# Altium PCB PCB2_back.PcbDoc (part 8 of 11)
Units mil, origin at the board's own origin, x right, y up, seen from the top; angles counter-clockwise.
Board outline 6299 x 3937 mil, 4 copper layers (TopLayer, GROUND, VCC, BottomLayer); 290 components, 470 nets, 2252 pads, 825 vias.
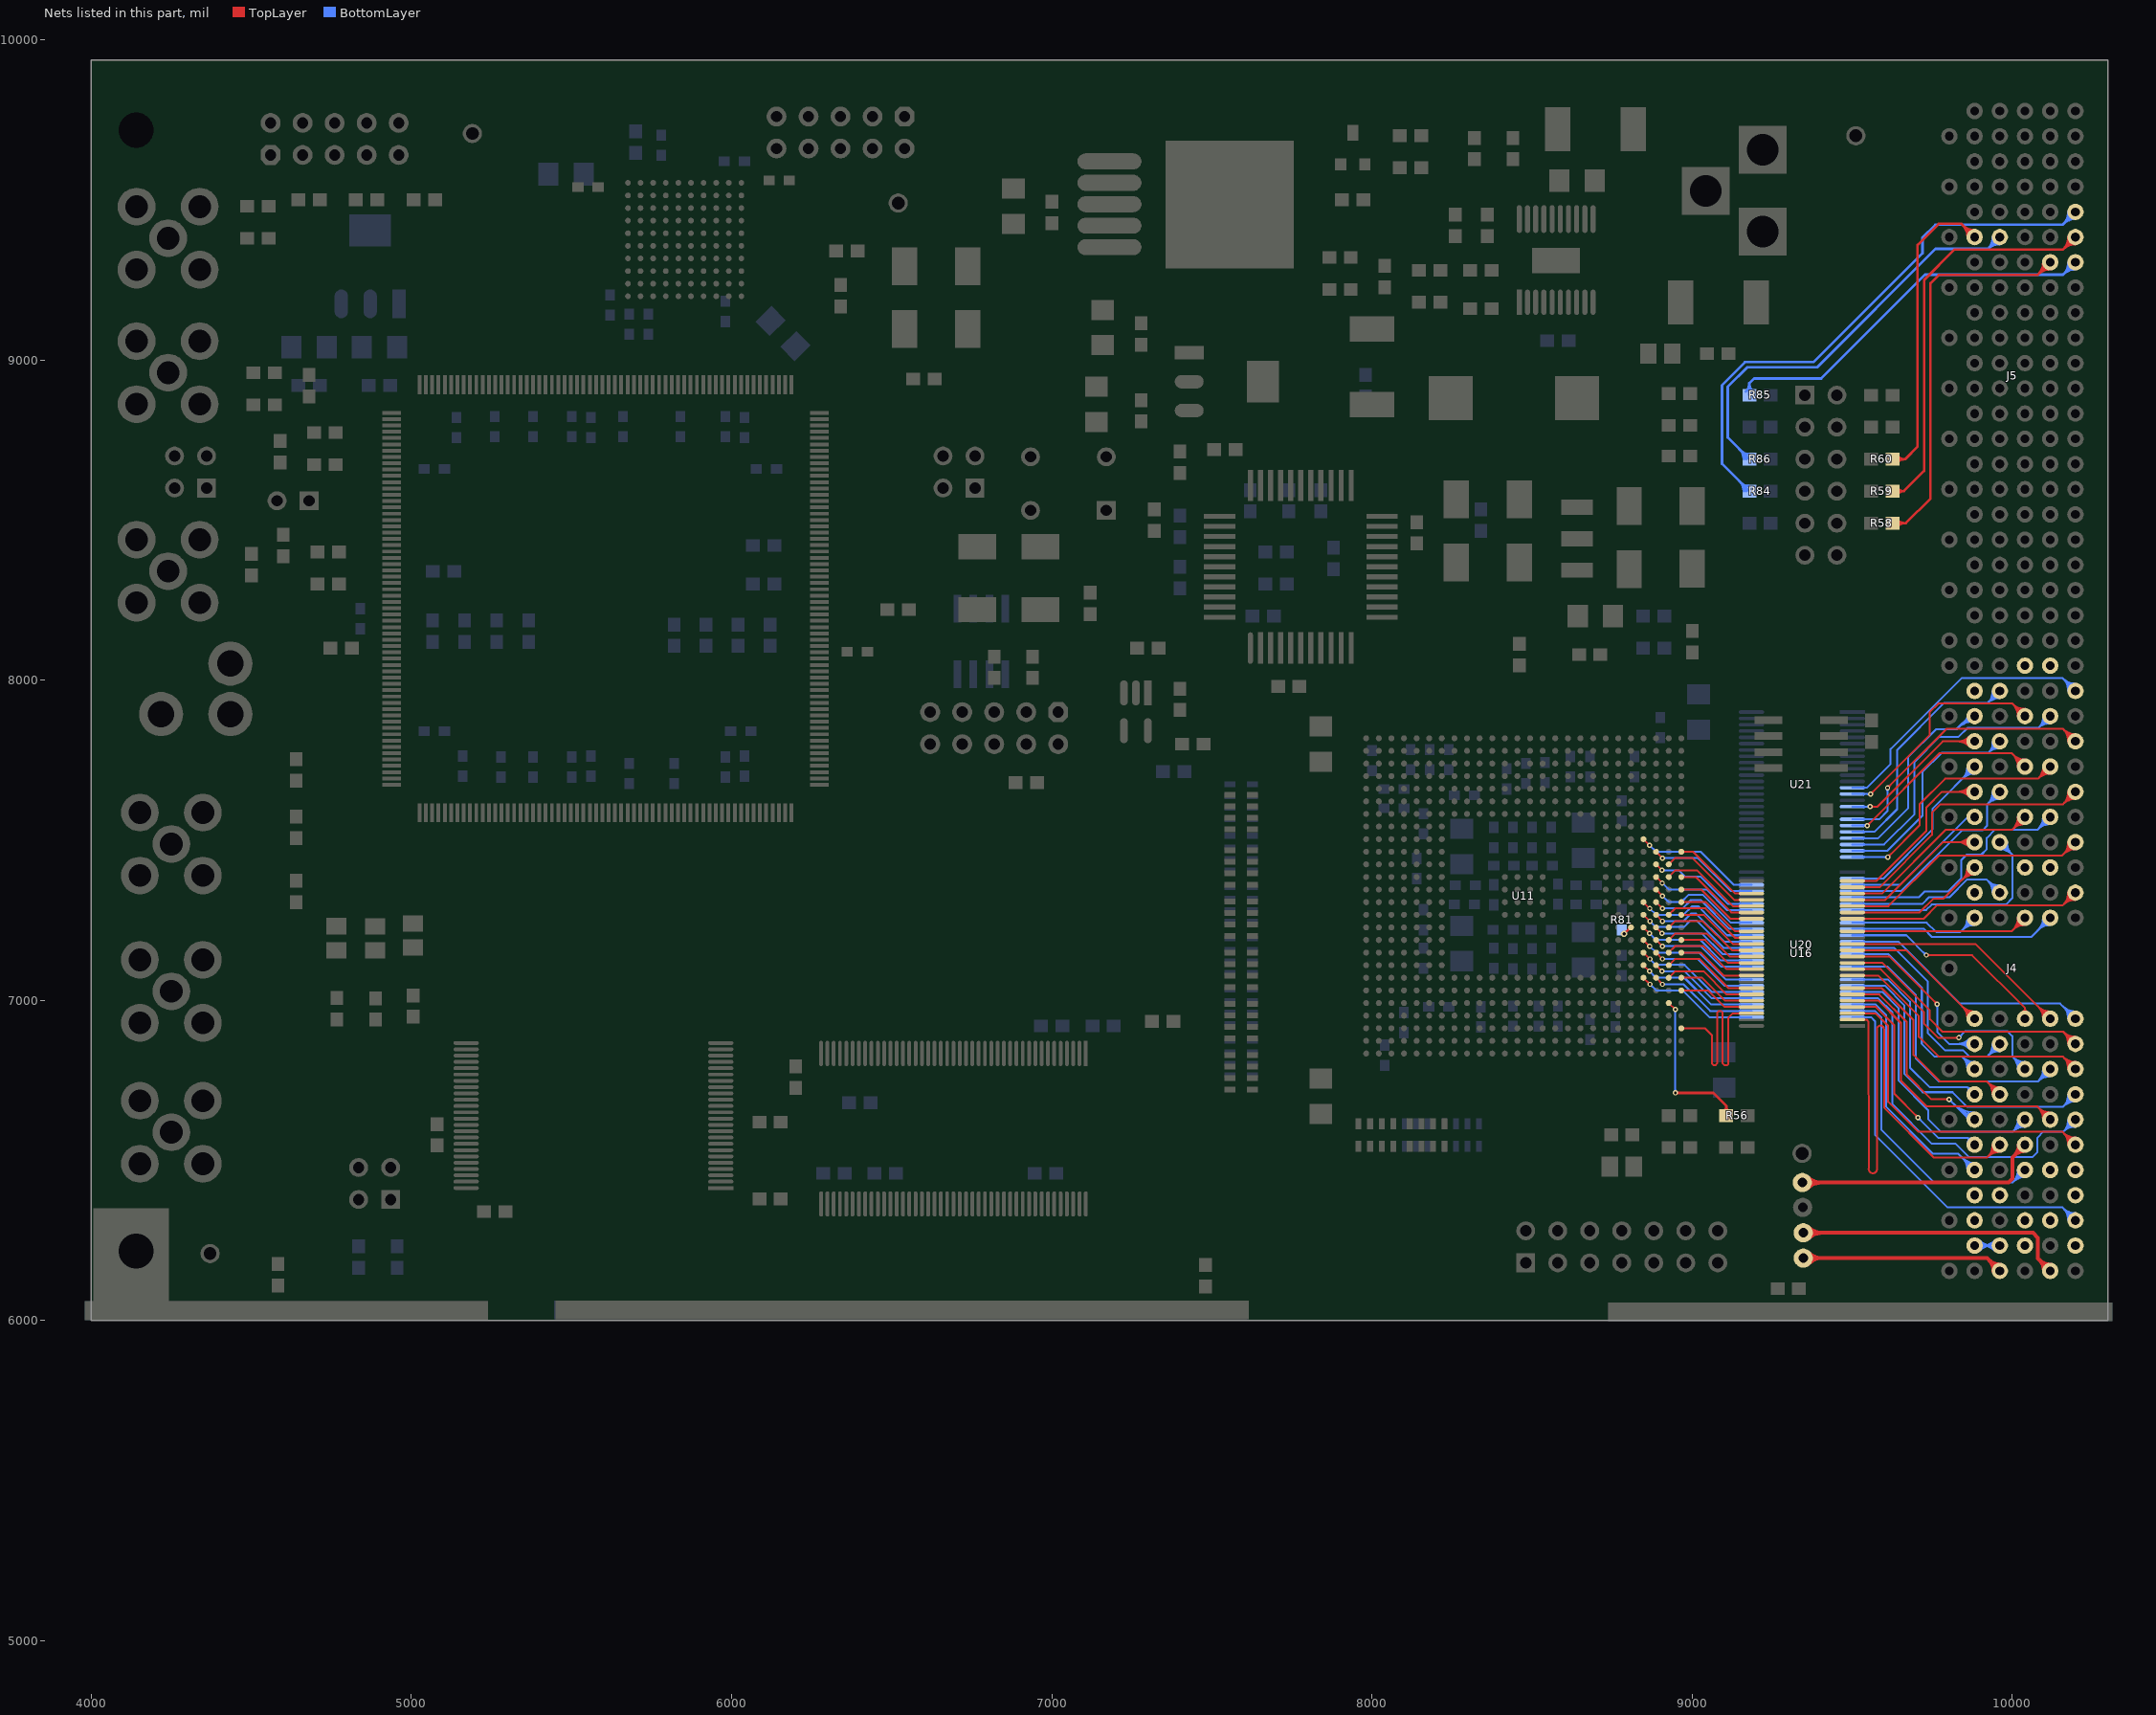
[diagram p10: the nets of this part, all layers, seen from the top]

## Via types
v1: diameter 16, hole 8, TopLayer to BottomLayer, 408 vias
v2: diameter 20, hole 10, TopLayer to BottomLayer, 221 vias
v3: diameter 24, hole 12, TopLayer to BottomLayer, 194 vias
v4: diameter 56.69, hole 56.69, TopLayer to BottomLayer, 2 vias

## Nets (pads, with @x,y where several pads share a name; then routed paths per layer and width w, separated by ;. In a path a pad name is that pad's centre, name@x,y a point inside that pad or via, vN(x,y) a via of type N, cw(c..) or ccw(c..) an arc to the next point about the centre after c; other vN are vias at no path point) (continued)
P_AD13: U11.U3 U20.45 | length 358.2
  TopLayer w6: U11.U3@8887.26,7463.92 v1(8907.18,7444)
  BottomLayer w6: v1(8907.18,7444) 9018,7444 9121.06,7340.94 U20.45@9185.04,7340.94 ; U20.45@9149.4,7339.17 ccw(c9145.12,7334.88) 9145.12,7340.95 ccw(c9145.12,7347.01) U20.45@9149.4,7342.72
P_AD14: U11.U1 U16.27 | length 282.6
  TopLayer w6: U11.U1@8966,7463.92 9003.08,7463.92 9133.61,7333.39 U16.27@9185.04,7333.39 ; U16.27@9149.4,7331.61 ccw(c9145.12,7327.32) 9145.12,7333.39 ccw(c9145.12,7339.45) U16.27@9149.4,7335.16
P_AD15: U11.T3 U20.43 | length 358.2
  TopLayer w6: U11.T3@8887.26,7424.55 v1(8905.81,7406)
  BottomLayer w6: v1(8905.81,7406) 8958,7406 8977.45,7386.55 9025.45,7386.55 9110.42,7301.57 U20.43@9185.04,7301.57 ; U20.43@9149.4,7299.8 ccw(c9145.12,7295.51) 9145.12,7301.58 ccw(c9145.12,7307.64) U20.43@9149.4,7303.35
P_AD16: U11.M3 U20.37 | length 361.8
  TopLayer w6: U11.M3@8887.26,7267.07 v1(8907.33,7247)
  BottomLayer w6: v1(8907.33,7247) 8972,7247 8996,7271 9012,7271 9099.53,7183.47 U20.37@9185.04,7183.47 ; U20.37@9149.4,7181.69 ccw(c9145.12,7177.4) 9145.12,7183.47 ccw(c9145.12,7189.53) U20.37@9149.4,7185.24
P_AD17: U11.M2 U16.34 | length 314.1
  TopLayer w6: U11.M2@8926.63,7267.07 8946.56,7287 9042,7287 9133.41,7195.59 U16.34@9185.04,7195.59 ; U16.34@9149.4,7193.81 ccw(c9145.12,7189.53) 9145.12,7195.59 ccw(c9145.12,7201.65) U16.34@9149.4,7197.37
P_AD18: U11.M4 U20.36 | length 405.2
  TopLayer w6: U11.M4@8847.89,7267.07 v1(8867.96,7247)
  BottomLayer w6: v1(8867.96,7247) 8885.96,7229 8974,7229 8993,7248 9014,7248 9098.22,7163.78 U20.36@9185.04,7163.78 ; U20.36@9149.4,7162 ccw(c9145.12,7157.72) 9145.12,7163.78 ccw(c9145.12,7169.84) U20.36@9149.4,7165.56
P_AD19: U11.L2 U16.36 | length 313.5
  TopLayer w6: U11.L2@8926.63,7227.7 8945.93,7247 9033,7247 9123.78,7156.22 U16.36@9185.04,7156.22 ; U16.36@9149.4,7154.44 ccw(c9145.12,7150.16) 9145.12,7156.22 ccw(c9145.12,7162.28) U16.36@9149.4,7158
P_AD20: U11.L3 U20.35 | length 341.9
  TopLayer w6: U11.L3@8887.26,7227.7 v1(8905.96,7209)
  BottomLayer w6: v1(8905.96,7209) 9030,7209 9094.91,7144.1 U20.35@9185.04,7144.1 ; U20.35@9149.4,7142.32 ccw(c9145.12,7138.03) 9145.12,7144.1 ccw(c9145.12,7150.16) U20.35@9149.4,7145.87
P_AD21: U11.K2 U16.37 | length 306.5
  TopLayer w6: U11.K2@8926.63,7188.33 8947.3,7209 9045,7209 9117.47,7136.53 U16.37@9185.04,7136.53 ; U16.37@9149.4,7134.76 ccw(c9145.12,7130.47) 9145.12,7136.53 ccw(c9145.12,7142.6) U16.37@9149.4,7138.31
P_AD22: U11.L4 U20.34 | length 389.5
  TopLayer w6: U11.L4@8847.89,7227.7 v1(8866.59,7209)
  BottomLayer w6: v1(8866.59,7209) 8886.59,7189 9025,7189 9089.59,7124.41 U20.34@9185.04,7124.41 ; U20.34@9149.4,7122.63 ccw(c9145.12,7118.35) 9145.12,7124.41 ccw(c9145.12,7130.47) U20.34@9149.4,7126.19
P_AD23: U11.K1 U16.38 | length 258.2
  TopLayer w6: U11.K1@8966,7188.33 9040.67,7188.33 9112.15,7116.85 U16.38@9185.04,7116.85 ; U16.38@9149.4,7115.07 ccw(c9145.12,7110.79) 9145.12,7116.85 ccw(c9145.12,7122.91) U16.38@9149.4,7118.63
P_AD24: U11.K4 U20.31 | length 397.6
  TopLayer w6: U11.K4@8847.89,7188.33 v1(8867.22,7169)
  BottomLayer w6: v1(8867.22,7169) 8887.22,7149 9021,7149 9104.65,7065.35 U20.31@9185.04,7065.35 ; U20.31@9149.4,7063.58 ccw(c9145.12,7059.29) 9145.12,7065.36 ccw(c9145.12,7071.42) U20.31@9149.4,7067.13
P_AD25: U11.J1 U16.40 | length 258.2
  TopLayer w6: U11.J1@8966,7148.96 9026.04,7148.96 9097.52,7077.48 U16.40@9185.04,7077.48 ; U16.40@9149.4,7075.7 ccw(c9145.12,7071.42) 9145.12,7077.48 ccw(c9145.12,7083.54) U16.40@9149.4,7079.26
P_AD26: U11.J3 U20.30 | length 350.1
  TopLayer w6: U11.J3@8887.26,7148.96 v1(8907.22,7129)
  BottomLayer w6: v1(8907.22,7129) 9017,7129 9100.33,7045.67 U20.30@9185.04,7045.67 ; U20.30@9149.4,7043.89 ccw(c9145.12,7039.61) 9145.12,7045.67 ccw(c9145.12,7051.73) U20.30@9149.4,7047.45
P_AD27: U11.H2 U16.42 | length 313.6
  TopLayer w6: U11.H2@8926.63,7109.59 8946.04,7129 9023,7129 9113.89,7038.11 U16.42@9185.04,7038.11 ; U16.42@9149.4,7036.33 ccw(c9145.12,7032.05) 9145.12,7038.11 ccw(c9145.12,7044.17) U16.42@9149.4,7039.89
P_AD28: U11.J4 U20.29 | length 397.6
  TopLayer w6: U11.J4@8847.89,7148.96 v1(8867.85,7129)
  BottomLayer w6: v1(8867.85,7129) 8885.85,7111 8976,7111 9061.01,7025.98 U20.29@9185.04,7025.98 ; U20.29@9149.4,7024.21 ccw(c9145.12,7019.92) 9145.12,7025.99 ccw(c9145.12,7032.05) U20.29@9149.4,7027.76
P_AD29: U11.G2 U16.43 | length 306.6
  TopLayer w6: U11.G2@8926.63,7070.22 8947.41,7091 9035,7091 9107.58,7018.43 U16.43@9185.04,7018.43 ; U16.43@9149.4,7016.65 ccw(c9145.12,7012.36) 9145.12,7018.43 ccw(c9145.12,7024.49) U16.43@9149.4,7020.2
P_AD30: U11.H3 U20.28 | length 350.1
  TopLayer w6: U11.H3@8887.26,7109.59 v1(8905.85,7091)
  BottomLayer w6: v1(8905.85,7091) 8976,7091 9060.7,7006.3 U20.28@9185.04,7006.3 ; U20.28@9149.4,7004.52 ccw(c9145.12,7000.24) 9145.12,7006.3 ccw(c9145.12,7012.36) U20.28@9149.4,7008.08
P_AD31: U11.G1 U16.44 | length 258.2
  TopLayer w6: U11.G1@8966,7070.22 9030.78,7070.22 9102.26,6998.74 U16.44@9185.04,6998.74 ; U16.44@9149.4,6996.96 ccw(c9145.12,6992.68) 9145.12,6998.74 ccw(c9145.12,7004.8) U16.44@9149.4,7000.52
P_CBE0: U11.V4 U20.46 | length 405.8
  TopLayer w6: U11.V4@8847.89,7503.29 v1(8867.18,7484)
  BottomLayer w6: v1(8867.18,7484) 8887.18,7464 9027,7464 9130.37,7360.63 U20.46@9185.04,7360.63 ; U20.46@9149.4,7358.85 ccw(c9145.12,7354.57) 9145.12,7360.63 ccw(c9145.12,7366.69) U20.46@9149.4,7362.41
P_CBE1: U11.T2 U16.28 | length 330
  TopLayer w6: U11.T2@8926.63,7424.55 8946.08,7444 9001,7444 9131.3,7313.7 U16.28@9185.04,7313.7 ; U16.28@9149.4,7311.92 ccw(c9145.12,7307.64) 9145.12,7313.7 ccw(c9145.12,7319.76) U16.28@9149.4,7315.48
P_CBE2: U11.M1 U16.35 | length 266.3
  TopLayer w6: U11.M1@8966,7267.07 9035.93,7267.07 9127.09,7175.9 U16.35@9185.04,7175.9 ; U16.35@9149.4,7174.13 ccw(c9145.12,7169.84) 9145.12,7175.91 ccw(c9145.12,7181.97) U16.35@9149.4,7177.68
P_CBE3: U11.J2 U16.39 | length 306
  TopLayer w6: U11.J2@8926.63,7148.96 8946.67,7169 9035,7169 9106.83,7097.16 U16.39@9185.04,7097.16 ; U16.39@9149.4,7095.39 ccw(c9145.12,7091.1) 9145.12,7097.16 ccw(c9145.12,7103.23) U16.39@9149.4,7098.94
P_CLK: U11.C1 U16.46 | length 805.9
  TopLayer w6: U11.C1@8966,6912.74 9039.26,6912.74 9062,6890 9062,6802 9066,6798 9073,6798 9078,6803 9078,6961 9084,6967 9090,6967 9095,6962 9095,6803 9101,6797 9109,6797 9113,6801 9113,6946 9126.37,6959.37 U16.46@9185.04,6959.37 ; U16.46@9149.4,6957.59 ccw(c9145.12,6953.31) 9145.12,6959.37 ccw(c9145.12,6965.43) U16.46@9149.4,6961.15
P_DEVSEL: U11.P1 U16.31 | length 266.3
  TopLayer w6: U11.P1@8966,7345.81 9028.19,7345.81 9119.35,7254.65 U16.31@9185.04,7254.65 ; U16.31@9149.4,7252.87 ccw(c9145.12,7248.58) 9145.12,7254.65 ccw(c9145.12,7260.71) U16.31@9149.4,7256.42
P_EN: R56.1 U11.E2 | length 571.2
  TopLayer w6: U11.E2@8926.63,6991.48 v1(8947,6971.11)
  TopLayer w8: v1(8947,6711) 9066,6711 9106.54,6670.46 ; v1@8949.83,6708.17 cw(c8956.66,6701.34) 8956.66,6711 cw(c8956.66,6720.66) v1@8949.83,6713.83 ; R56.1@9097.42,6652.77 ccw(c9084.79,6670.46) 9106.54,6670.46 ; R56.1@9106.54,6640 9106.54,6670.46 ; R56.1@9115.65,6652.77 cw(c9128.28,6670.46) 9106.54,6670.46
  BottomLayer w6: v1@8943.46,6714.54 ccw(c8934.93,6723.07) 8947,6723.07 ccw(c8959.07,6723.07) v1@8950.54,6714.54 ; v1(8947,6711) v1(8947,6971.11)
P_FRAME: U11.N4 U20.38 | length 411.3
  TopLayer w6: U11.N4@8847.89,7306.44 v1(8867.33,7287)
  BottomLayer w6: v1(8867.33,7287) 8887.33,7267 8973,7267 8999,7293 9020,7293 9036,7277 ; 9035.5,7276.5 9108.85,7203.15 U20.38@9185.04,7203.15 ; U20.38@9149.4,7201.37 ccw(c9145.12,7197.09) 9145.12,7203.15 ccw(c9145.12,7209.21) U20.38@9149.4,7204.93
P_GNT: U11.H4 U20.27 | length 397.6
  TopLayer w6: U11.H4@8847.89,7109.59 v1(8866.48,7091)
  BottomLayer w6: v1(8866.48,7091) 8886.48,7071 8975,7071 9059.39,6986.61 U20.27@9185.04,6986.61 ; U20.27@9149.4,6984.84 ccw(c9145.12,6980.55) 9145.12,6986.62 ccw(c9145.12,6992.68) U20.27@9149.4,6988.39
P_IDSEL: U11.K3 U20.33 | length 341.9
  TopLayer w6: U11.K3@8887.26,7188.33 v1(8906.59,7169)
  BottomLayer w6: v1(8906.59,7169) 9026,7169 9090.27,7104.73 U20.33@9185.04,7104.73 ; U20.33@9149.4,7102.95 ccw(c9145.12,7098.66) 9145.12,7104.73 ccw(c9145.12,7110.79) U20.33@9149.4,7106.5
P_INTA: U11.G4 U20.25 | length 397.6
  TopLayer w6: U11.G4@8847.89,7070.22 v1(8868.11,7050)
  BottomLayer w6: v1(8868.11,7050) 8887.11,7031 8970,7031 9053.75,6947.24 U20.25@9185.04,6947.24 ; U20.25@9149.4,6945.47 ccw(c9145.12,6941.18) 9145.12,6947.24 ccw(c9145.12,6953.31) U20.25@9149.4,6949.02
P_IRDY: U11.N1 U16.33 | length 266.3
  TopLayer w6: U11.N1@8966,7306.44 9042.56,7306.44 9133.73,7215.27 U16.33@9185.04,7215.27 ; U16.33@9149.4,7213.5 ccw(c9145.12,7209.21) 9145.12,7215.28 ccw(c9145.12,7221.34) U16.33@9149.4,7217.05
P_PAR: U11.P3 U20.40 | length 368.3
  TopLayer w6: U11.P3@8887.26,7345.81 v1(8907.07,7326)
  BottomLayer w6: v1(8907.07,7326) 8926.07,7307 8966,7307 8988,7329 9034,7329 9120.48,7242.52 U20.40@9185.04,7242.52 ; U20.40@9149.4,7240.74 ccw(c9145.12,7236.46) 9145.12,7242.52 ccw(c9145.12,7248.58) U20.40@9149.4,7244.3
P_PERR: U11.R1 U16.30 | length 274.5
  TopLayer w6: U11.R1@8966,7385.18 9010.82,7385.18 9121.67,7274.33 U16.30@9185.04,7274.33 ; U16.30@9149.4,7272.55 ccw(c9145.12,7268.27) 9145.12,7274.33 ccw(c9145.12,7280.39) U16.30@9149.4,7276.11
P_REQ: U11.F1 U16.45 | length 250
  TopLayer w6: U11.F1@8966,7030.85 9049.15,7030.85 9100.94,6979.06 U16.45@9185.04,6979.06 ; U16.45@9149.4,6977.28 ccw(c9145.12,6972.99) 9145.12,6979.06 ccw(c9145.12,6985.12) U16.45@9149.4,6980.83
P_RST: U11.G3 U20.26 | length 350.1
  TopLayer w6: U11.G3@8887.26,7070.22 v1(8907.48,7050)
  BottomLayer w6: v1(8907.48,7050) 8973,7050 9056.07,6966.93 U20.26@9185.04,6966.93 ; U20.26@9149.4,6965.15 ccw(c9145.12,6960.87) 9145.12,6966.93 ccw(c9145.12,6972.99) U20.26@9149.4,6968.71
P_SERR: U11.R2 U16.29 | length 322.1
  TopLayer w6: U11.R2@8926.63,7385.18 8946.45,7405 9016,7405 9126.99,7294.02 U16.29@9185.04,7294.02 ; U16.29@9149.4,7292.24 ccw(c9145.12,7287.95) 9145.12,7294.02 ccw(c9145.12,7300.08) U16.29@9149.4,7295.79
P_STOP: U11.R3 U20.42 | length 350.1
  TopLayer w6: U11.R3@8887.26,7385.18 v1(8906.44,7366)
  BottomLayer w6: v1(8906.44,7366) 8926.44,7346 9044,7346 9108.11,7281.89 U20.42@9185.04,7281.89 ; U20.42@9149.4,7280.11 ccw(c9145.12,7275.83) 9145.12,7281.89 ccw(c9145.12,7287.95) U20.42@9149.4,7283.67
P_TRDY: U11.N3 U20.39 | length 363.5
  TopLayer w6: U11.N3@8887.26,7306.44 v1(8906.7,7287)
  BottomLayer w6: v1(8906.7,7287) 8970,7287 8996,7313 9026,7313 9116.17,7222.84 U20.39@9185.04,7222.84 ; U20.39@9149.4,7221.06 ccw(c9145.12,7216.77) 9145.12,7222.84 ccw(c9145.12,7228.9) U20.39@9149.4,7224.61
PCI_EEAI: R81.1 U11.L5 | length 29.2
  TopLayer w8: v2(8787,7208) U11.L5@8808.52,7227.7
PXI_3.3V: J4.C6 pad.1@9344,6431 | length 948.5
  TopLayer w12: pad.1@9344,6431 9988,6431 10000,6443 10000,6509.51 J4.C6@10039.37,6548.88 ; pad.1@9360.97,6414.03 cw(c9401.94,6373.06) 9401.94,6431 cw(c9401.94,6488.94) pad.1@9360.97,6447.97 ; J4.C6@10019.78,6548.88 cw(c9972.48,6548.88) 10005.93,6515.44 cw(c10039.37,6482) J4.C6@10039.37,6529.29
PXI_+12V: J4.D1 pad.4 | length 795.4
  TopLayer w12: pad.4@9347,6195 9920.81,6195 J4.D1@9960.63,6155.18 ; pad.4@9363.97,6178.03 cw(c9404.94,6137.06) 9404.94,6195 cw(c9404.94,6252.94) pad.4@9363.97,6211.97 ; J4.D1@9941.04,6155.18 ccw(c9893.74,6155.18) 9927.19,6188.62 ccw(c9960.63,6222.07) J4.D1@9960.63,6174.77
PXI_-12V: J4.B1 pad.3 | length 1023.5
  TopLayer w12: pad.3@9347,6274 10064,6274 10080,6258 10080,6193.29 J4.B1@10118.11,6155.18 ; pad.3@9363.97,6257.03 cw(c9404.94,6216.06) 9404.94,6274 cw(c9404.94,6331.94) pad.3@9363.97,6290.97 ; J4.B1@10098.52,6155.18 ccw(c10051.22,6155.18) 10084.67,6188.62 ccw(c10118.11,6222.07) J4.B1@10118.11,6174.77
PXI_ACK64#: J4.E24
PXI_AD0: J4.D24 U21.20 | length 913.8
  BottomLayer w6: U21.20@9500,7525.98 9569,7525.98 9640,7596.98 9640,7782 9786,7928 9922.49,7928 J4.D24@9965.49,7971 ; U21.20@9535.63,7524.21 cw(c9539.92,7519.92) 9539.92,7525.99 cw(c9539.92,7532.05) U21.20@9535.63,7527.76 ; 9932.63,7938.14 ccw(c9905.08,7965.69) J4.D24@9944.04,7966.05 ; 9932.67,7938.18 cw(c9960.27,7910.58) J4.D24@9960.52,7949.62 ; J4.D24@9938.04,7966 cw(c9885.05,7965.51) 9922.52,7928.03 cw(c9960.14,7890.41) J4.D24@9960.48,7943.62
PXI_AD1: J4.A24 U21.13 | length 1061.2
  BottomLayer w6: U21.13@9500,7663.78 9544.78,7663.78 9619.67,7738.67 9619.67,7784.67 9842,8007 10155.99,8007 J4.A24@10196.85,7966.14 ; U21.13@9535.63,7662 cw(c9539.92,7657.72) 9539.92,7663.78 cw(c9539.92,7669.84) U21.13@9535.63,7665.56 ; 10158.18,8004.81 ccw(c10196.85,8043.49) J4.A24@10196.85,7988.8 ; 10158.33,8004.66 cw(c10119.87,7966.21) J4.A24@10174.26,7966.21 ; 10168.42,7994.57 ccw(c10196.85,8023) J4.A24@10196.85,7982.8 ; 10168.57,7994.42 cw(c10140.36,7966.21) J4.A24@10180.26,7966.21 ; 10178.66,7984.33 ccw(c10196.85,8002.52) J4.A24@10196.85,7976.8
PXI_AD2: J4.E23 U21.21 | length 802.4
  BottomLayer w6: U21.21@9500,7506.3 9581,7506.3 9674,7599.3 9674,7759 9761.41,7846.41 9825.41,7846.41 9866.4,7887.4 J4.E23@9881.89,7887.4 ; U21.21@9535.63,7504.52 cw(c9539.92,7500.24) 9539.92,7506.3 cw(c9539.92,7512.36) U21.21@9535.63,7508.08 ; 9827.82,7848.82 cw(c9881.08,7795.56) J4.E23@9881.74,7870.88 ; 9837.93,7858.93 cw(c9881.25,7815.61) J4.E23@9881.8,7876.87 ; 9848.05,7869.05 cw(c9881.43,7835.67) J4.E23@9881.85,7882.87 ; 9854.23,7875.23 ccw(c9842,7887.47) J4.E23@9859.3,7887.47
PXI_AD3: J4.C23 U21.14 | length 930.8
  TopLayer w6: v1(9557.09,7644.1) 9741,7828 9741,7899 9769,7927 9999.77,7927 J4.C23@10039.37,7887.4 ; v1@9557.09,7649.1 ccw(c9557.09,7661.17) 9565.63,7652.63 ccw(c9574.17,7644.1) v1@9562.1,7644.1 ; 10000.7,7926.07 ccw(c10039.37,7964.75) J4.C23@10039.37,7910.06 ; 10000.85,7925.92 cw(c9962.39,7887.47) J4.C23@10016.78,7887.47 ; 10010.94,7915.83 ccw(c10039.37,7944.26) J4.C23@10039.37,7904.06 ; 10011.09,7915.68 cw(c9982.88,7887.47) J4.C23@10022.78,7887.47 ; 10021.18,7905.59 ccw(c10039.37,7923.78) J4.C23@10039.37,7898.06
  BottomLayer w6: U21.14@9500,7644.1 v1(9557.09,7644.1) ; U21.14@9535.63,7642.32 cw(c9539.92,7638.03) 9539.92,7644.1 cw(c9539.92,7650.16) U21.14@9535.63,7645.87 ; v1@9553.56,7640.56 ccw(c9545.02,7632.02) 9545.02,7644.1 ccw(c9545.02,7656.17) v1@9553.56,7647.63
PXI_AD4: J4.B23 U21.22 | length 1024.6
  BottomLayer w6: U21.22@9500,7486.61 9599,7486.61 9694,7581.61 9694,7744 9772.9,7822.9 9831.9,7822.9 9860,7851 10081.71,7851 J4.B23@10118.11,7887.4 ; U21.22@9535.63,7484.84 cw(c9539.92,7480.55) 9539.92,7486.62 cw(c9539.92,7492.68) U21.22@9535.63,7488.39 ; 10091.39,7860.68 ccw(c10066.82,7885.25) J4.B23@10101.54,7886.75 ; 10091.43,7860.72 cw(c10116.04,7836.11) J4.B23@10117.44,7870.89 ; J4.B23@10095.54,7886.49 cw(c10048.32,7884.45) 10081.74,7851.03 cw(c10115.29,7817.48) J4.B23@10117.2,7864.89
PXI_AD5: J4.E22 U21.16 | length 682.6
  TopLayer w6: v1(9555.73,7604.73) 9578.73,7604.73 9782.66,7808.66 J4.E22@9881.89,7808.72 ; v1@9559.26,7601.19 cw(c9567.8,7592.65) 9567.8,7604.73 cw(c9567.8,7616.8) v1@9559.26,7608.26 ; 9827.2,7808.66 ccw(c9827.2,7863.42) J4.E22@9865.92,7824.7 ; 9827.5,7808.66 cw(c9827.5,7754.34) J4.E22@9865.92,7792.75 ; 9841.68,7808.66 ccw(c9841.68,7848.93) J4.E22@9870.16,7820.46 ; 9841.99,7808.66 cw(c9841.99,7768.82) J4.E22@9870.16,7796.99 ; 9856.17,7808.66 ccw(c9856.17,7834.44) J4.E22@9874.4,7816.21
  BottomLayer w6: U21.16@9500,7604.73 v1(9555.73,7604.73) ; U21.16@9535.63,7602.95 cw(c9539.92,7598.66) 9539.92,7604.73 cw(c9539.92,7610.79) U21.16@9535.63,7606.5 ; v1@9552.19,7601.19 ccw(c9543.65,7592.65) 9543.65,7604.73 ccw(c9543.65,7616.8) v1@9552.19,7608.26
PXI_AD6: J4.D22 U21.23 | length 823.5
  BottomLayer w6: U21.23@9500,7466.93 9610,7466.93 9719,7575.93 9719,7713 9779,7773 9924.97,7773 J4.D22@9960.63,7808.72 ; U21.23@9535.63,7465.15 cw(c9539.92,7460.87) 9539.92,7466.93 cw(c9539.92,7472.99) U21.23@9535.63,7468.71 ; 9934.45,7782.49 ccw(c9911.11,7805.83) J4.D22@9944.07,7807.76 ; 9934.49,7782.52 cw(c9957.88,7759.14) J4.D22@9959.71,7792.16 ; J4.D22@9938.08,7807.41 cw(c9893.25,7804.79) 9925,7773.03 cw(c9956.88,7741.15) J4.D22@9959.38,7786.17
PXI_AD7: J4.A22 U21.18 | length 1088.6
  TopLayer w6: v1(9610,7663) 9795,7848 10157.51,7848 J4.A22@10196.85,7808.72 ; v1@9610,7668 ccw(c9610,7680.07) 9618.54,7671.54 ccw(c9627.07,7663) v1@9615,7663 ; 10158.18,7847.33 ccw(c10196.85,7886.01) J4.A22@10196.85,7831.32 ; 10158.33,7847.18 cw(c10119.87,7808.72) J4.A22@10174.26,7808.72 ; 10168.42,7837.09 ccw(c10196.85,7865.52) J4.A22@10196.85,7825.32 ; 10168.57,7836.94 cw(c10140.36,7808.72) J4.A22@10180.26,7808.72 ; 10178.66,7826.85 ccw(c10196.85,7845.04) J4.A22@10196.85,7819.32
  BottomLayer w6: U21.18@9500,7565.35 9584.35,7565.35 9610,7591 v1(9610,7663) ; U21.18@9535.63,7563.58 cw(c9539.92,7559.29) 9539.92,7565.36 cw(c9539.92,7571.42) U21.18@9535.63,7567.13 ; v1@9606.46,7659.46 cw(c9597.93,7650.93) 9610,7650.93 cw(c9622.07,7650.93) v1@9613.54,7659.46
PXI_AD8: J4.C21 U21.19 | length 866.8
  TopLayer w6: v1(9546.67,7545.67) 9773,7772 9997.29,7772 J4.C21@10039.37,7729.92 ; v1@9546.67,7550.67 ccw(c9546.67,7562.74) 9555.21,7554.21 ccw(c9563.74,7545.67) v1@9551.67,7545.67 ; 10000.7,7768.59 ccw(c10039.37,7807.27) J4.C21@10039.37,7752.58 ; 10000.85,7768.44 cw(c9962.39,7729.98) J4.C21@10016.78,7729.98 ; 10010.94,7758.35 ccw(c10039.37,7786.78) J4.C21@10039.37,7746.58 ; 10011.09,7758.2 cw(c9982.88,7729.98) J4.C21@10022.78,7729.98 ; 10021.18,7748.11 ccw(c10039.37,7766.29) J4.C21@10039.37,7740.58
  BottomLayer w6: U21.19@9500,7545.67 v1(9546.67,7545.67) ; U21.19@9535.63,7543.89 cw(c9539.92,7539.61) 9539.92,7545.67 cw(c9539.92,7551.73) U21.19@9535.63,7547.45 ; v1@9543.13,7542.13 ccw(c9534.6,7533.6) 9534.6,7545.67 ccw(c9534.6,7557.74) v1@9543.13,7549.21
PXI_AD9: J4.B21 U21.24 | length 966.1
  TopLayer w6: v1(9611.25,7447.24) 9710.28,7546.28 9710.28,7612.28 9790,7692 10080.19,7692 J4.B21@10118.11,7729.92 ; v1@9611.25,7452.24 ccw(c9611.25,7464.32) 9619.78,7455.78 ccw(c9628.32,7447.24) v1@9616.25,7447.24 ; 10090.27,7702.08 ccw(c10063.11,7729.25) J4.B21@10101.52,7729.76 ; 10090.31,7702.12 cw(c10117.53,7674.91) J4.B21@10117.93,7713.4 ; J4.B21@10095.52,7729.68 cw(c10043.27,7728.98) 10080.22,7692.03 cw(c10117.32,7654.94) J4.B21@10117.87,7707.4
  BottomLayer w6: U21.24@9500,7447.24 v1(9611.25,7447.24) ; U21.24@9535.63,7445.47 cw(c9539.92,7441.18) 9539.92,7447.24 cw(c9539.92,7453.31) U21.24@9535.63,7449.02 ; v1@9607.71,7443.71 ccw(c9599.17,7435.17) 9599.17,7447.24 ccw(c9599.17,7459.32) v1@9607.71,7450.78
PXI_AD10: J4.E20 U16.24 | length 718.3
  TopLayer w6: U16.24@9500,7372.76 9574.75,7372.76 9731.25,7529.25 9731.25,7602.25 9780.18,7651.18 J4.E20@9881.89,7651.24 ; U16.24@9535.63,7370.98 cw(c9539.92,7366.69) 9539.92,7372.76 cw(c9539.92,7378.82) U16.24@9535.63,7374.53 ; 9827.2,7651.18 ccw(c9827.2,7705.93) J4.E20@9865.92,7667.22 ; 9827.5,7651.18 cw(c9827.5,7596.86) J4.E20@9865.92,7635.27 ; 9841.68,7651.18 ccw(c9841.68,7691.45) J4.E20@9870.16,7662.98 ; 9841.99,7651.18 cw(c9841.99,7611.34) J4.E20@9870.16,7639.51 ; 9856.17,7651.18 ccw(c9856.17,7676.96) J4.E20@9874.4,7658.73
PXI_AD11: J4.D20 U20.4 | length 806.4
  BottomLayer w6: U20.4@9500,7340.94 9651.94,7340.94 9842,7531 9907,7531 9921,7545 9921,7611.55 J4.D20@9960.63,7651.24 ; U20.4@9535.63,7339.17 cw(c9539.92,7334.88) 9539.92,7340.95 cw(c9539.92,7347.01) U20.4@9535.63,7342.72 ; 9922.02,7612.57 ccw(c9883.35,7651.24) J4.D20@9938.04,7651.24 ; 9922.17,7612.72 cw(c9960.63,7574.27) J4.D20@9960.63,7628.65 ; 9932.26,7622.82 ccw(c9903.83,7651.24) J4.D20@9944.04,7651.24 ; 9932.42,7622.97 cw(c9960.63,7594.75) J4.D20@9960.63,7634.65 ; 9942.51,7633.06 ccw(c9924.32,7651.24) J4.D20@9950.04,7651.24
PXI_AD12: J4.A20 U16.23 | length 1039.1
  TopLayer w6: U16.23@9500,7353.07 9585.07,7353.07 9748.62,7516.62 9748.62,7585.62 9775,7612 10157.67,7612 J4.A20@10196.85,7651.24 ; U16.23@9535.63,7351.29 cw(c9539.92,7347.01) 9539.92,7353.07 cw(c9539.92,7359.13) U16.23@9535.63,7354.85 ; 10158.24,7612.57 ccw(c10119.57,7651.24) J4.A20@10174.26,7651.24 ; 10158.39,7612.72 cw(c10196.85,7574.27) J4.A20@10196.85,7628.65 ; 10168.48,7622.82 ccw(c10140.05,7651.24) J4.A20@10180.26,7651.24 ; 10168.64,7622.97 cw(c10196.85,7594.75) J4.A20@10196.85,7634.65 ; 10178.73,7633.06 ccw(c10160.54,7651.24) J4.A20@10186.26,7651.24
PXI_AD13: J4.E19 U20.3 | length 479.1
  BottomLayer w6: U20.3@9500,7360.63 9648.63,7360.63 9860.44,7572.44 J4.E19@9881.89,7572.44 ; U20.3@9535.63,7358.85 cw(c9539.92,7354.57) 9539.92,7360.63 cw(c9539.92,7366.69) U20.3@9535.63,7362.41
PXI_AD14: J4.C19 U16.22 | length 816.7
  TopLayer w6: U16.22@9500,7333.39 9592.39,7333.39 9791,7532 9998.93,7532 J4.C19@10039.37,7572.44 ; U16.22@9535.63,7331.61 cw(c9539.92,7327.32) 9539.92,7333.39 cw(c9539.92,7339.45) U16.22@9535.63,7335.16 ; 10000.76,7533.83 ccw(c9962.09,7572.5) J4.C19@10016.78,7572.5 ; 10000.91,7533.98 cw(c10039.37,7495.53) J4.C19@10039.37,7549.91 ; 10011,7544.07 ccw(c9982.57,7572.5) J4.C19@10022.78,7572.5 ; 10011.16,7544.23 cw(c10039.37,7516.01) J4.C19@10039.37,7555.91 ; 10021.25,7554.32 ccw(c10003.06,7572.5) J4.C19@10028.78,7572.5
PXI_AD15: J4.B19 U20.5 | length 953.8
  BottomLayer w6: U20.5@9500,7321.26 9707.37,7321.26 9726,7339.89 9798.89,7339.89 9840,7381 9840,7437 9858,7455 9903,7455 9920,7472 9920,7507 9946,7533 10078.67,7533 J4.B19@10118.11,7572.44 ; U20.5@9535.63,7319.48 cw(c9539.92,7315.2) 9539.92,7321.26 cw(c9539.92,7327.32) U20.5@9535.63,7323.04 ; 10079.5,7533.83 ccw(c10040.83,7572.5) J4.B19@10095.52,7572.5 ; 10079.65,7533.98 cw(c10118.11,7495.53) J4.B19@10118.11,7549.91 ; 10089.74,7544.07 ccw(c10061.31,7572.5) J4.B19@10101.52,7572.5 ; 10089.9,7544.23 cw(c10118.11,7516.01) J4.B19@10118.11,7555.91 ; 10099.99,7554.32 ccw(c10081.8,7572.5) J4.B19@10107.52,7572.5
PXI_AD16: J4.C11 U20.11 | length 745.1
  TopLayer w6: v1(9731,7141) 9874,7141 10039.37,6975.63 ; v1@9734.54,7137.46 cw(c9743.07,7128.93) 9743.07,7141 cw(c9743.07,7153.07) v1@9734.54,7144.54 ; J4.C11@10031.17,6963.63 ccw(c10026.49,6975.63) 10039.37,6975.63 ; J4.C11@10039.37,6942.52 10039.37,6975.63 ; J4.C11@10047.57,6963.63 cw(c10052.25,6975.63) 10039.37,6975.63
  BottomLayer w6: U20.11@9500,7203.15 9668.85,7203.15 v1(9731,7141) ; U20.11@9535.63,7201.37 cw(c9539.92,7197.09) 9539.92,7203.15 cw(c9539.92,7209.21) U20.11@9535.63,7204.93 ; v1@9726,7141 ccw(c9713.93,7141) 9722.46,7149.54 ccw(c9731,7158.07) v1@9731,7146
PXI_AD17: J4.B11 U16.14 | length 893.1
  TopLayer w6: U16.14@9500,7175.9 9884.72,7175.9 J4.B11@10118.11,6942.52 ; U16.14@9535.63,7174.13 cw(c9539.92,7169.84) 9539.92,7175.91 cw(c9539.92,7181.97) U16.14@9535.63,7177.68 ; 10079.44,6981.19 ccw(c10118.11,7019.86) J4.B11@10118.11,6965.17 ; 10079.59,6981.04 cw(c10041.13,6942.58) J4.B11@10095.52,6942.58 ; 10089.68,6970.95 ccw(c10118.11,6999.38) J4.B11@10118.11,6959.17 ; 10089.83,6970.8 cw(c10061.62,6942.58) J4.B11@10101.52,6942.58 ; 10099.92,6960.71 ccw(c10118.11,6978.89) J4.B11@10118.11,6953.17
PXI_AD18: J4.A11 U20.12 | length 975
  BottomLayer w6: U20.12@9500,7183.47 9643.53,7183.47 9837,6990 10149.37,6990 J4.A11@10196.85,6942.52 ; U20.12@9535.63,7181.69 cw(c9539.92,7177.4) 9539.92,7183.47 cw(c9539.92,7189.53) U20.12@9535.63,7185.24 ; 10158.18,6981.19 ccw(c10196.85,7019.86) J4.A11@10196.85,6965.17 ; 10158.33,6981.04 cw(c10119.87,6942.58) J4.A11@10174.26,6942.58 ; 10168.42,6970.95 ccw(c10196.85,6999.38) J4.A11@10196.85,6959.17 ; 10168.57,6970.8 cw(c10140.36,6942.58) J4.A11@10180.26,6942.58 ; 10178.66,6960.71 ccw(c10196.85,6978.89) J4.A11@10196.85,6953.17
PXI_AD19: J4.E10 U16.12 | length 762.1
  TopLayer w6: U16.12@9500,7136.53 9616.47,7136.53 v1(9765,6988) ; U16.12@9535.63,7134.76 cw(c9539.92,7130.47) 9539.92,7136.53 cw(c9539.92,7142.6) U16.12@9535.63,7138.31 ; v1@9760,6988 ccw(c9747.93,6988) 9756.46,6996.54 ccw(c9765,7005.07) v1@9765,6993
  BottomLayer w6: v1@9761.46,6984.46 cw(c9752.93,6975.93) 9765,6975.93 cw(c9777.07,6975.93) v1@9768.54,6984.46 ; v1(9765,6988) 9765,6901 9802.22,6863.78 J4.E10@9881.89,6863.84 ; 9827.2,6863.78 ccw(c9827.2,6918.53) J4.E10@9865.92,6879.82 ; 9827.5,6863.78 cw(c9827.5,6809.46) J4.E10@9865.92,6847.87 ; 9841.68,6863.78 ccw(c9841.68,6904.05) J4.E10@9870.16,6875.57 ; 9841.99,6863.78 cw(c9841.99,6823.94) J4.E10@9870.16,6852.11 ; 9856.17,6863.78 ccw(c9856.17,6889.56) J4.E10@9874.4,6871.33
PXI_AD20: J4.D10 U20.13 | length 890.2
  BottomLayer w6: U20.13@9500,7163.78 9630.22,7163.78 9736,7058 9736,6897.39 9789,6844.39 9845.61,6844.39 9866,6824 9920.85,6824 J4.D10@9960.63,6863.84 ; U20.13@9535.63,7162 cw(c9539.92,7157.72) 9539.92,7163.78 cw(c9539.92,7169.84) U20.13@9535.63,7165.56 ; 9922.02,6825.17 ccw(c9883.35,6863.84) J4.D10@9938.04,6863.84 ; 9922.17,6825.32 cw(c9960.63,6786.87) J4.D10@9960.63,6841.25 ; 9932.26,6835.41 ccw(c9903.83,6863.84) J4.D10@9944.04,6863.84 ; 9932.42,6835.57 cw(c9960.63,6807.35) J4.D10@9960.63,6847.25 ; 9942.51,6845.66 ccw(c9924.32,6863.84) J4.D10@9950.04,6863.84
PXI_AD21: J4.A10 U16.11 | length 973.8
  TopLayer w6: U16.11@9500,7116.85 9594.15,7116.85 9742,6969 9742,6941 9781,6902 10158.63,6902 J4.A10@10196.85,6863.84 ; U16.11@9535.63,7115.07 cw(c9539.92,7110.79) 9539.92,7116.85 cw(c9539.92,7122.91) U16.11@9535.63,7118.63 ; 10168.82,6891.81 cw(c10141.19,6864.19) J4.A10@10180.26,6863.94 ; 10168.78,6891.85 ccw(c10196.35,6919.43) J4.A10@10196.7,6880.43 ; J4.A10@10174.26,6863.98 ccw(c10121.01,6864.31) 10158.66,6901.97 ccw(c10196.17,6939.47) J4.A10@10196.65,6886.43
PXI_AD22: J4.E9 U20.14 | length 812
  BottomLayer w6: U20.14@9500,7144.1 9612.91,7144.1 9717,7040 9717,6864 9757,6824 9842.93,6824 J4.E9@9881.89,6785.04 ; U20.14@9535.63,7142.32 cw(c9539.92,7138.03) 9539.92,7144.1 cw(c9539.92,7150.16) U20.14@9535.63,7145.87 ; 9843.22,6823.71 ccw(c9881.89,6862.38) J4.E9@9881.89,6807.69 ; 9843.37,6823.56 cw(c9804.91,6785.1) J4.E9@9859.3,6785.1 ; 9853.46,6813.47 ccw(c9881.89,6841.9) J4.E9@9881.89,6801.69 ; 9853.61,6813.32 cw(c9825.4,6785.1) J4.E9@9865.3,6785.1 ; 9863.7,6803.23 ccw(c9881.89,6821.41) J4.E9@9881.89,6795.69
PXI_AD23: J4.C9 U16.10 | length 939.3
  TopLayer w6: U16.10@9500,7097.16 9588.83,7097.16 9724,6962 9724,6927 9768,6883 v1(9833,6883) ; U16.10@9535.63,7095.39 cw(c9539.92,7091.1) 9539.92,7097.16 cw(c9539.92,7103.23) U16.10@9535.63,7098.94 ; v1@9829.46,6879.46 ccw(c9820.93,6870.93) 9820.93,6883 ccw(c9820.93,6895.07) v1@9829.46,6886.54
  BottomLayer w6: v1@9832.87,6888 ccw(c9832.56,6900.07) 9841.31,6891.75 ccw(c9850.07,6883.44) v1@9838,6883.13 ; v1(9833,6883) 9852,6903 9985,6903 10000,6888 10000,6824.47 J4.C9@10039.37,6785.1 ; J4.C9@10016.78,6785.1 ccw(c9962.24,6785.1) 10000.81,6823.67 ccw(c10039.37,6862.23) J4.C9@10039.37,6807.69 ; J4.C9@10022.78,6785.1 ccw(c9982.73,6785.1) 10011.05,6813.42 ccw(c10039.37,6841.75) J4.C9@10039.37,6801.69
PXI_AD24: J4.E8 U20.18 | length 684.8
  BottomLayer w6: U20.18@9500,7065.35 9610.65,7065.35 9680,6996 9680,6790 9742,6728 9860.19,6728 J4.E8@9881.89,6706.3 ; U20.18@9535.63,7063.58 cw(c9539.92,7059.29) 9539.92,7065.36 cw(c9539.92,7071.42) U20.18@9535.63,7067.13 ; J4.E8@9861.9,6716.89 ccw(c9853.54,6721.29) 9860.22,6727.97 ccw(c9866.88,6734.62) J4.E8@9871.29,6726.31
PXI_AD25: J4.D8 U16.7 | length 840.2
  TopLayer w6: U16.7@9500,7038.11 9590.89,7038.11 9691.07,6937.93 9691.07,6828.93 9773,6747 9919.93,6747 J4.D8@9960.63,6706.3 ; U16.7@9535.63,7036.33 cw(c9539.92,7032.05) 9539.92,7038.11 cw(c9539.92,7044.17) U16.7@9535.63,7039.89 ; 9921.96,6744.97 ccw(c9960.63,6783.64) J4.D8@9960.63,6728.95 ; 9922.11,6744.82 cw(c9883.65,6706.36) J4.D8@9938.04,6706.36 ; 9932.2,6734.73 ccw(c9960.63,6763.16) J4.D8@9960.63,6722.95 ; 9932.35,6734.58 cw(c9904.14,6706.36) J4.D8@9944.04,6706.36 ; 9942.44,6724.49 ccw(c9960.63,6742.67) J4.D8@9960.63,6716.95
PXI_AD26: J4.A8 U20.19 | length 1151.1
  BottomLayer w6: U20.19@9500,7045.67 9601.33,7045.67 9663,6984 9663,6770 9720,6713 9813,6713 9858,6668 10158.55,6668 J4.A8@10196.85,6706.3 ; U20.19@9535.63,7043.89 cw(c9539.92,7039.61) 9539.92,7045.67 cw(c9539.92,7051.73) U20.19@9535.63,7047.45 ; 10168.74,6678.19 ccw(c10140.91,6706.01) J4.A8@10180.26,6706.26 ; 10168.78,6678.22 cw(c10196.65,6650.35) J4.A8@10196.79,6689.77 ; J4.A8@10174.26,6706.22 cw(c10120.74,6705.88) 10158.59,6668.03 cw(c10196.58,6630.04) J4.A8@10196.77,6683.77
PXI_AD27: J4.E7 U16.6 | length 958.4
  TopLayer w6: U16.6@9500,7018.43 9584.58,7018.43 9670,6933 9670,6768 9747,6691 v1(9802,6691) ; U16.6@9535.63,7016.65 cw(c9539.92,7012.36) 9539.92,7018.43 cw(c9539.92,7024.49) U16.6@9535.63,7020.2 ; v1@9798.46,6687.46 ccw(c9789.93,6678.93) 9789.93,6691 ccw(c9789.93,6703.07) v1@9798.46,6694.54
  BottomLayer w6: v1@9802,6686 cw(c9802,6673.93) 9810.54,6682.46 cw(c9819.07,6691) v1@9807,6691 ; v1@9802,6689 v1@9804,6689 ; v1(9802,6691) 9865.44,6627.56 J4.E7@9881.89,6627.62 ; 9815.14,6677.86 ccw(c9881.89,6744.61) J4.E7@9881.89,6650.21 ; 9825.38,6667.62 ccw(c9881.89,6724.13) J4.E7@9881.89,6644.21 ; 9835.62,6657.38 ccw(c9881.89,6703.64) J4.E7@9881.89,6638.21 ; 9845.87,6647.13 ccw(c9881.89,6683.16) J4.E7@9881.89,6632.21 ; 9855,6638 cw(c9844.62,6627.62) J4.E7@9859.3,6627.62 ; 9856.11,6636.89 ccw(c9881.89,6662.67) J4.E7@9881.89,6626.21
PXI_AD28: J4.C7 U20.20 | length 1063.1
  BottomLayer w6: U20.20@9500,7025.98 9594.01,7025.98 9645,6975 9645,6749 9737,6657 9737,6629 9777,6589 10000.81,6589 J4.C7@10039.37,6627.62 ; U20.20@9535.63,7024.21 cw(c9539.92,7019.92) 9539.92,7025.99 cw(c9539.92,7032.05) U20.20@9535.63,7027.76 ; 10000.84,6589.03 ccw(c9962.37,6627.5) J4.C7@10016.78,6627.59 ; 10000.91,6589.1 cw(c10039.37,6550.65) J4.C7@10039.37,6605.03 ; 10011.07,6599.25 ccw(c9982.78,6627.53) J4.C7@10022.78,6627.6 ; 10011.16,6599.34 cw(c10039.37,6571.13) J4.C7@10039.37,6611.03 ; 10021.29,6609.47 ccw(c10003.19,6627.57) J4.C7@10028.78,6627.61
PXI_AD29: J4.B7 U16.5 | length 1055.6
  TopLayer w6: U16.5@9500,6998.74 9582.26,6998.74 9652,6929 9652,6749 9732,6669 10076.67,6669 J4.B7@10118.11,6627.62 ; U16.5@9535.63,6996.96 cw(c9539.92,6992.68) 9539.92,6998.74 cw(c9539.92,7004.8) U16.5@9535.63,7000.52 ; 10079.44,6666.23 ccw(c10118.11,6704.9) J4.B7@10118.11,6650.21 ; 10079.59,6666.08 cw(c10041.13,6627.62) J4.B7@10095.52,6627.62 ; 10089.68,6655.99 ccw(c10118.11,6684.42) J4.B7@10118.11,6644.21 ; 10089.83,6655.84 cw(c10061.62,6627.62) J4.B7@10101.52,6627.62 ; 10099.92,6645.75 ccw(c10118.11,6663.93) J4.B7@10118.11,6638.21
PXI_AD30: J4.A7 U20.21 | length 1297.8
  BottomLayer w6: U20.21@9500,7006.3 9580.7,7006.3 9625,6962 9625,6675 9747,6553 9822,6553 9865,6510 10062,6510 10078,6526 10078,6571 10097,6590 10159.29,6590 J4.A7@10196.85,6627.62 ; U20.21@9535.63,7004.52 cw(c9539.92,7000.24) 9539.92,7006.3 cw(c9539.92,7012.36) U20.21@9535.63,7008.08 ; 10159.32,6590.03 cw(c10195.56,6553.8) J4.A7@10196.46,6605.03 ; 10159.33,6590.03 ccw(c10123.23,6626.13) J4.A7@10174.26,6627.16 ; 10169.28,6599.99 ccw(c10142.75,6626.52) J4.A7@10180.26,6627.28 ; 10169.32,6600.03 cw(c10195.9,6573.44) J4.A7@10196.56,6611.03
PXI_AD31: J4.E6 U16.4 | length 758.8
  TopLayer w6: U16.4@9500,6979.06 9573.94,6979.06 9631,6922 9631,6708 v1(9705,6634) ; U16.4@9535.63,6977.28 cw(c9539.92,6972.99) 9539.92,6979.06 cw(c9539.92,6985.12) U16.4@9535.63,6980.83 ; v1@9700,6634 ccw(c9687.93,6634) 9696.46,6642.54 ccw(c9705,6651.07) v1@9705,6639
  BottomLayer w6: v1@9705,6629 cw(c9705,6616.93) 9713.54,6625.46 cw(c9722.07,6634) v1@9710,6634 ; v1(9705,6634) 9768,6571 9859.71,6571 J4.E6@9881.89,6548.82 ; J4.E6@9861.68,6558.99 ccw(c9852.4,6563.63) 9859.74,6570.97 ccw(c9867.05,6578.28) J4.E6@9871.71,6569.05
PXI_BRSVP1A5: J4.A5
PXI_BRSVP1B5: J4.B5
PXI_C/BE0#: J4.E21 U20.2 | length 747.3
  BottomLayer w6: U20.2@9500,7380.31 9597,7380.31 9751,7534.31 9751,7599.03 J4.E21@9884.97,7733 ; U20.2@9535.63,7378.54 cw(c9539.92,7374.25) 9539.92,7380.32 cw(c9539.92,7386.38) U20.2@9535.63,7382.09 ; 9843.28,7691.31 ccw(c9804.61,7729.98) J4.E21@9859.3,7729.98 ; 9843.43,7691.46 cw(c9881.89,7653.01) J4.E21@9881.89,7707.39 ; 9853.52,7701.56 ccw(c9825.09,7729.98) J4.E21@9865.3,7729.98 ; 9853.68,7701.71 cw(c9881.89,7673.49) J4.E21@9881.89,7713.39 ; 9863.77,7711.8 ccw(c9845.58,7729.98) J4.E21@9871.3,7729.98
PXI_C/BE1#: J4.E18 U16.21 | length 645.6
  TopLayer w6: U16.21@9500,7313.7 9602.7,7313.7 9782.7,7493.7 J4.E18@9892.7,7493.7 ; U16.21@9535.63,7311.92 cw(c9539.92,7307.64) 9539.92,7313.7 cw(c9539.92,7319.76) U16.21@9535.63,7315.48 ; 9827.2,7493.7 ccw(c9827.2,7548.45) J4.E18@9865.92,7509.74 ; 9827.5,7493.7 cw(c9827.5,7439.38) J4.E18@9865.92,7477.79 ; 9841.68,7493.7 ccw(c9841.68,7533.97) J4.E18@9870.16,7505.5 ; 9841.99,7493.7 cw(c9841.99,7453.86) J4.E18@9870.16,7482.03 ; 9856.17,7493.7 ccw(c9856.17,7519.48) J4.E18@9874.4,7501.25
PXI_C/BE2#: J4.E11 U16.13 | length 648.7
  TopLayer w6: U16.13@9500,7156.22 9668.19,7156.22 J4.E11@9881.89,6942.52 ; U16.13@9535.63,7154.44 cw(c9539.92,7150.16) 9539.92,7156.22 cw(c9539.92,7162.28) U16.13@9535.63,7158 ; 9843.22,6981.19 ccw(c9881.89,7019.86) J4.E11@9881.89,6965.17 ; 9843.37,6981.04 cw(c9804.91,6942.58) J4.E11@9859.3,6942.58 ; 9853.46,6970.95 ccw(c9881.89,6999.38) J4.E11@9881.89,6959.17 ; 9853.61,6970.8 cw(c9825.4,6942.58) J4.E11@9865.3,6942.58 ; 9863.7,6960.71 ccw(c9881.89,6978.89) J4.E11@9881.89,6953.17
PXI_C/BE3#: J4.A9 U16.9 | length 1034.4
  TopLayer w6: U16.9@9500,7077.48 9581.52,7077.48 9708,6951 9708,6886 9769,6825 10156.89,6825 J4.A9@10196.85,6785.04 ; U16.9@9535.63,7075.7 cw(c9539.92,7071.42) 9539.92,7077.48 cw(c9539.92,7083.54) U16.9@9535.63,7079.26 ; 10158.18,6823.71 ccw(c10196.85,6862.38) J4.A9@10196.85,6807.69 ; 10158.33,6823.56 cw(c10119.87,6785.1) J4.A9@10174.26,6785.1 ; 10168.42,6813.47 ccw(c10196.85,6841.9) J4.A9@10196.85,6801.69 ; 10168.57,6813.32 cw(c10140.36,6785.1) J4.A9@10180.26,6785.1 ; 10178.66,6803.23 ccw(c10196.85,6821.41) J4.A9@10196.85,6795.69
PXI_CLK10: J5.E17 R60.1 | length 1139.3
  TopLayer w8: R60.1@9625.46,8690 9665,8690 ; R60.1@9638.59,8678.97 cw(c9665,8652.86) 9665,8690 ; R60.1@9638.59,8701.03 ccw(c9665,8727.14) 9665,8690 ; J5.E17@9860.3,9383.53 ccw(c9808.17,9383.53) 9845.03,9420.39 ccw(c9881.89,9457.24) J5.E17@9881.89,9405.12 ; J5.E17@9868.3,9383.53 ccw(c9835.49,9383.53) 9858.69,9406.73 ccw(c9881.89,9429.93) J5.E17@9881.89,9397.12 ; J5.E17@9881.89,9383.53 9840.42,9425 9770,9425 9704,9359 9704,8729 9665,8690
PXI_DEVSEL#: J4.A16 U16.18 | length 908.9
  TopLayer w6: U16.18@9500,7254.65 9722.65,7254.65 9765,7297 10157.63,7297 J4.A16@10196.85,7336.22 ; U16.18@9535.63,7252.87 cw(c9539.92,7248.58) 9539.92,7254.65 cw(c9539.92,7260.71) U16.18@9535.63,7256.42 ; 10158.24,7297.61 ccw(c10119.57,7336.28) J4.A16@10174.26,7336.28 ; 10158.39,7297.76 cw(c10196.85,7259.31) J4.A16@10196.85,7313.69 ; 10168.48,7307.85 ccw(c10140.05,7336.28) J4.A16@10180.26,7336.28 ; 10168.64,7308.01 cw(c10196.85,7279.79) J4.A16@10196.85,7319.69 ; 10178.73,7318.1 ccw(c10160.54,7336.28) J4.A16@10186.26,7336.28
PXI_ENUM#: J4.C25
PXI_FRAME#: J4.B15 U20.10 | length 836.3
  BottomLayer w6: U20.10@9500,7222.84 9724.17,7222.84 9749,7198 10058.63,7198 J4.B15@10121.63,7261 ; U20.10@9535.63,7221.06 cw(c9539.92,7216.77) 9539.92,7222.84 cw(c9539.92,7228.9) U20.10@9535.63,7224.61 ; 10079.5,7218.87 ccw(c10040.83,7257.54) J4.B15@10095.52,7257.54 ; 10079.65,7219.02 cw(c10118.11,7180.57) J4.B15@10118.11,7234.95 ; 10089.74,7229.11 ccw(c10061.31,7257.54) J4.B15@10101.52,7257.54 ; 10089.9,7229.27 cw(c10118.11,7201.05) J4.B15@10118.11,7240.95 ; 10099.99,7239.36 ccw(c10081.8,7257.54) J4.B15@10107.52,7257.54
PXI_GNT#: J4.E5 U20.22 | length 942.3
  BottomLayer w6: U20.22@9500,6986.61 9573.39,6986.61 9606,6954 9606,6667 9752,6521 9830.97,6521 J4.E5@9881.89,6470.14 ; U20.22@9535.63,6984.84 cw(c9539.92,6980.55) 9539.92,6986.62 cw(c9539.92,6992.68) U20.22@9535.63,6988.39 ; 9843.22,6508.75 ccw(c9881.89,6547.42) J4.E5@9881.89,6492.73 ; 9843.37,6508.6 cw(c9804.91,6470.14) J4.E5@9859.3,6470.14 ; 9853.46,6498.51 ccw(c9881.89,6526.94) J4.E5@9881.89,6486.73 ; 9853.61,6498.36 cw(c9825.4,6470.14) J4.E5@9865.3,6470.14 ; 9863.7,6488.27 ccw(c9881.89,6506.45) J4.E5@9881.89,6480.73
PXI_IDSEL: J4.B9 U20.16 | length 1077.2
  BottomLayer w6: U20.16@9500,7104.73 9610.27,7104.73 9699,7016 9699,6818 9771,6746 10079.07,6746 J4.B9@10118.11,6785.04 ; U20.16@9535.63,7102.95 cw(c9539.92,7098.66) 9539.92,7104.73 cw(c9539.92,7110.79) U20.16@9535.63,7106.5 ; 10079.5,6746.43 ccw(c10040.83,6785.1) J4.B9@10095.52,6785.1 ; 10079.65,6746.58 cw(c10118.11,6708.13) J4.B9@10118.11,6762.51 ; 10089.74,6756.67 ccw(c10061.31,6785.1) J4.B9@10101.52,6785.1 ; 10089.9,6756.82 cw(c10118.11,6728.61) J4.B9@10118.11,6768.51 ; 10099.99,6766.92 ccw(c10081.8,6785.1) J4.B9@10107.52,6785.1
PXI_INTA#: J4.A3 U20.24 | length 1331.9
  BottomLayer w6: U20.24@9500,6947.24 9558.75,6947.24 9571,6935 9571,6580 9798,6353 10156.51,6353 J4.A3@10196.85,6312.66 ; U20.24@9535.63,6945.47 cw(c9539.92,6941.18) 9539.92,6947.24 cw(c9539.92,6953.31) U20.24@9535.63,6949.02 ; J4.A3@10174.26,6312.66 ccw(c10119.72,6312.66) 10158.29,6351.23 ccw(c10196.85,6389.79) J4.A3@10196.85,6335.25 ; J4.A3@10180.26,6312.66 ccw(c10140.21,6312.66) 10168.53,6340.98 ccw(c10196.85,6369.3) J4.A3@10196.85,6329.25 ; J4.A3@10196.88,6312.63 J4.A3@10201.25,6317
PXI_INTB#: J4.B3
PXI_INTC#: J4.C3
PXI_INTD#: J4.E3
PXI_INTP: J4.D4
PXI_INTS: J4.E4
PXI_IPMB_PWR: J4.A4
PXI_IPMB_SCL: J4.B17
PXI_IPMB_SDA: J4.C17
PXI_IRDY#: J4.C15 U16.16 | length 735.2
  TopLayer w6: U16.16@9500,7215.27 9997.16,7215.27 J4.C15@10039.37,7257.54 ; U16.16@9535.63,7213.5 cw(c9539.92,7209.21) 9539.92,7215.28 cw(c9539.92,7221.34) U16.16@9535.63,7217.05 ; 10000.76,7218.87 ccw(c9962.09,7257.54) J4.C15@10016.78,7257.54 ; 10000.91,7219.02 cw(c10039.37,7180.57) J4.C15@10039.37,7234.95 ; 10011,7229.11 ccw(c9982.57,7257.54) J4.C15@10022.78,7257.54 ; 10011.16,7229.27 cw(c10039.37,7201.05) J4.C15@10039.37,7240.95 ; 10021.25,7239.36 ccw(c10003.06,7257.54) J4.C15@10028.78,7257.54
PXI_LOCK#: J4.E16
PXI_PAR: J4.D18 U20.7 | length 884.7
  BottomLayer w6: U20.7@9500,7281.89 9730.89,7281.89 9748,7299 9980,7299 10000,7319 10000,7454.33 J4.D18@9960.63,7493.7 ; U20.7@9535.63,7280.11 cw(c9539.92,7275.83) 9539.92,7281.89 cw(c9539.92,7287.95) U20.7@9535.63,7283.67 ; J4.D18@9960.63,7471.17 cw(c9960.63,7416.79) 9999.09,7455.24 ; J4.D18@9960.63,7477.17 cw(c9960.63,7437.27) 9988.84,7465.49 ; J4.D18@9971.22,7493.76 ccw(c9996.94,7493.76) 9978.75,7475.58 ; J4.D18@9977.22,7493.76 ccw(c10017.43,7493.76) 9989,7465.33 ; J4.D18@9983.22,7493.76 ccw(c10037.91,7493.76) 9999.24,7455.09
PXI_PCLK: J4.D6 U16.2 | length 1892.4
  TopLayer w6: U16.2@9500,6939.69 9544.32,6939.69 9551,6933 9551.15,6474.98 ccw(c9564,6473) 9577,6473 9577,6911 cw(c9588,6910) 9599.05,6910 ; U16.2@9535.63,6937.91 cw(c9539.92,6933.62) 9539.92,6939.69 cw(c9539.92,6945.75) U16.2@9535.63,6941.46 ; 9599,6910 9599,6665 9755,6509 9920.81,6509 J4.D6@9960.63,6548.82 ; 9922.02,6510.21 ccw(c9883.35,6548.88) J4.D6@9938.04,6548.88 ; 9922.17,6510.36 cw(c9960.63,6471.9) J4.D6@9960.63,6526.29 ; 9932.26,6520.45 ccw(c9903.83,6548.88) J4.D6@9944.04,6548.88 ; 9932.42,6520.6 cw(c9960.63,6492.39) J4.D6@9960.63,6532.29 ; 9942.51,6530.69 ccw(c9924.32,6548.88) J4.D6@9950.04,6548.88
PXI_PERR#: J4.E17 U16.19 | length 618.5
  TopLayer w6: U16.19@9500,7274.33 9710.33,7274.33 9754,7318 9784.93,7318 J4.E17@9881.89,7415.02 ; U16.19@9535.63,7272.55 cw(c9539.92,7268.27) 9539.92,7274.33 cw(c9539.92,7280.39) U16.19@9535.63,7276.11 ; 9843.28,7376.35 ccw(c9804.61,7415.02) J4.E17@9859.3,7415.02 ; 9843.43,7376.5 cw(c9881.89,7338.05) J4.E17@9881.89,7392.43 ; 9853.52,7386.59 ccw(c9825.09,7415.02) J4.E17@9865.3,7415.02 ; 9853.68,7386.75 cw(c9881.89,7358.53) J4.E17@9881.89,7398.43 ; 9863.77,7396.84 ccw(c9845.58,7415.02) J4.E17@9871.3,7415.02
PXI_REQ64#: J4.B25
PXI_REQ#: J4.A6 U16.3 | length 1184
  TopLayer w6: U16.3@9500,6959.37 9572.63,6959.37 9612,6920 9612,6683 9706,6589 10156.67,6589 J4.A6@10196.85,6548.82 ; U16.3@9535.63,6957.59 cw(c9539.92,6953.31) 9539.92,6959.37 cw(c9539.92,6965.43) U16.3@9535.63,6961.15 ; 10158.18,6587.49 ccw(c10196.85,6626.16) J4.A6@10196.85,6571.47 ; 10158.33,6587.34 cw(c10119.87,6548.88) J4.A6@10174.26,6548.88 ; 10168.42,6577.25 ccw(c10196.85,6605.68) J4.A6@10196.85,6565.47 ; 10168.57,6577.1 cw(c10140.36,6548.88) J4.A6@10180.26,6548.88 ; 10178.66,6567.01 ccw(c10196.85,6585.19) J4.A6@10196.85,6559.47
PXI_RST#: J4.C5 U20.23 | length 1137.6
  BottomLayer w6: U20.23@9500,6966.93 9570.07,6966.93 9590,6947 9590,6596 9754,6432 10001.29,6432 J4.C5@10039.37,6470.14 ; U20.23@9535.63,6965.15 cw(c9539.92,6960.87) 9539.92,6966.93 cw(c9539.92,6972.99) U20.23@9535.63,6968.71 ; 10011.42,6442.13 ccw(c9983.98,6469.56) J4.C5@10022.78,6469.97 ; 10011.46,6442.17 cw(c10038.95,6414.68) J4.C5@10039.24,6453.55 ; J4.C5@10016.78,6469.91 cw(c9964.01,6469.35) 10001.33,6432.03 cw(c10038.79,6394.57) J4.C5@10039.2,6447.55
PXI_SERR#: J4.A18 U16.20 | length 957.9
  TopLayer w6: U16.20@9500,7294.02 9613.01,7294.02 9771,7452 10155.15,7452 J4.A18@10196.85,7493.7 ; U16.20@9535.63,7292.24 cw(c9539.92,7287.95) 9539.92,7294.02 cw(c9539.92,7300.08) U16.20@9535.63,7295.79 ; 10158.24,7455.09 ccw(c10119.57,7493.76) J4.A18@10174.26,7493.76 ; 10158.39,7455.24 cw(c10196.85,7416.79) J4.A18@10196.85,7471.17 ; 10168.48,7465.33 ccw(c10140.05,7493.76) J4.A18@10180.26,7493.76 ; 10168.64,7465.49 cw(c10196.85,7437.27) J4.A18@10196.85,7477.17 ; 10178.73,7475.58 ccw(c10160.54,7493.76) J4.A18@10186.26,7493.76
PXI_START: J5.D17 R86.2 | length 1506.6
  BottomLayer w8: 9148.4,8720.14 cw(c9118.26,8690) R86.2@9160.88,8690 ; 9153.15,8715.38 ccw(c9176.57,8738.8) R86.2@9176.57,8705.68 ; R86.2@9162.06,8706.48 cw(c9145.58,8690) R86.2@9168.88,8690 ; R86.2@9178.54,8690 9111,8757.54 9111,8916 9172,8977 9390,8977 9760,9347 9924.1,9347 ; J5.D17@9939.04,9383.39 cw(c9888.04,9383.06) 9924.1,9347 ; J5.D17@9947.04,9383.44 cw(c9914.94,9383.24) 9937.64,9360.54 cw(c9960.34,9337.84) J5.D17@9960.54,9369.94 ; J5.D17@9960.49,9361.94 ccw(c9960.16,9310.94) 9924.1,9347 ; J5.D17@9960.63,9383.53 9924.1,9347
PXI_STOP#: J4.D16 U20.6 | length 687.1
  BottomLayer w6: U20.6@9500,7301.57 9719.58,7301.57 9740.03,7322.03 9803.03,7322.03 9858,7377 9919.85,7377 J4.D16@9960.63,7336.22 ; U20.6@9535.63,7299.8 cw(c9539.92,7295.51) 9539.92,7301.58 cw(c9539.92,7307.64) U20.6@9535.63,7303.35 ; 9921.96,7374.89 ccw(c9960.63,7413.56) J4.D16@9960.63,7358.87 ; 9922.11,7374.74 cw(c9883.65,7336.28) J4.D16@9938.04,7336.28 ; 9932.2,7364.65 ccw(c9960.63,7393.08) J4.D16@9960.63,7352.87 ; 9932.35,7364.5 cw(c9904.14,7336.28) J4.D16@9944.04,7336.28 ; 9942.44,7354.41 ccw(c9960.63,7372.59) J4.D16@9960.63,7346.87
PXI_TCK: J4.A2
PXI_TDIO: J4.D2 J4.E2 | length 416.4
  BottomLayer w6: J4.E2@9881.89,6233.92 J4.D2@9960.63,6233.92 ; J4.E2@9889.38,6241.41 ccw(c9907.61,6259.64) 9907.61,6233.86 ; J4.E2@9893.62,6222.19 cw(c9921.79,6194.02) 9921.79,6233.86 ; J4.E2@9893.62,6245.65 ccw(c9922.09,6274.13) 9922.09,6233.86 ; J4.E2@9897.86,6217.95 cw(c9936.28,6179.53) J4.D2@9936.28,6233.86 ; J4.E2@9897.86,6249.89 ccw(c9936.58,6288.61) J4.D2@9936.58,6233.86 ; J4.E2@9905.94,6233.86 ccw(c9905.94,6288.61) J4.D2@9944.66,6249.89 ; J4.E2@9906.24,6233.86 cw(c9906.24,6179.53) J4.D2@9944.66,6217.95 ; 9920.42,6233.86 ccw(c9920.42,6274.13) J4.D2@9948.9,6245.65 ; 9920.73,6233.86 cw(c9920.73,6194.02) J4.D2@9948.9,6222.19 ; 9934.91,6233.86 ccw(c9934.91,6259.64) J4.D2@9953.14,6241.41
PXI_TMS: J4.C2
PXI_TRDY#: J4.E15 U20.9 | length 607.1
  BottomLayer w6: U20.9@9500,7242.52 9732.48,7242.52 9762,7213 9837.41,7213 J4.E15@9893.41,7269 ; U20.9@9535.63,7240.74 cw(c9539.92,7236.46) 9539.92,7242.52 cw(c9539.92,7248.58) U20.9@9535.63,7244.3 ; 9843.28,7218.87 ccw(c9804.61,7257.54) J4.E15@9859.3,7257.54 ; 9843.43,7219.02 cw(c9881.89,7180.57) J4.E15@9881.89,7234.95 ; 9853.52,7229.11 ccw(c9825.09,7257.54) J4.E15@9865.3,7257.54 ; 9853.68,7229.27 cw(c9881.89,7201.05) J4.E15@9881.89,7240.95 ; 9863.77,7239.36 ccw(c9845.58,7257.54) J4.E15@9871.3,7257.54
PXI_TRIG0: J5.B16 R58.1 | length 1416.7
  TopLayer w8: R58.1@9625.46,8490 9667,8490 9744,8567 9744,9239 9770,9265 10078.32,9265 J5.B16@10118.11,9304.79 ; R58.1@9638.52,8478.91 cw(c9665.3,8452.13) 9665.3,8490 cw(c9665.3,8527.87) R58.1@9638.52,8501.09 ; J5.B16@10096.52,9304.79 cw(c10044.4,9304.79) 10081.25,9267.93 cw(c10118.11,9231.07) J5.B16@10118.11,9283.2 ; J5.B16@10104.52,9304.79 cw(c10071.71,9304.79) 10094.91,9281.59 cw(c10118.11,9258.39) J5.B16@10118.11,9291.2
PXI_TRIG1: J5.A16 R85.2 | length 1404.2
  BottomLayer w8: R85.2@9167.51,8901.16 ccw(c9141.47,8927.53) 9178.54,8927.53 ; R85.2@9178.54,8890 9178.54,8927.54 ; R85.2@9189.56,8901.16 cw(c9215.6,8927.53) 9178.54,8927.53 ; J5.A16@10175.26,9304.79 cw(c10123.14,9304.79) 10159.99,9267.93 cw(c10196.85,9231.07) J5.A16@10196.85,9283.2 ; J5.A16@10183.26,9304.79 cw(c10150.45,9304.79) 10173.65,9281.59 cw(c10196.85,9258.39) J5.A16@10196.85,9291.2 ; J5.A16@10196.85,9304.79 10158.06,9266 9727,9266 9403,8942 9193,8942 9178.54,8927.54
PXI_TRIG2: J5.A17 R59.1 | length 1431.7
  TopLayer w8: R59.1@9625.46,8590 9661,8590 ; R59.1@9639.46,8579.94 cw(c9661,8561.93) 9661,8590 ; R59.1@9639.46,8600.06 ccw(c9661,8618.07) 9661,8590 ; J5.A17@10175.26,9383.53 cw(c10123.14,9383.53) 10159.99,9346.67 cw(c10196.85,9309.81) J5.A17@10196.85,9361.94 ; J5.A17@10183.26,9383.53 cw(c10150.45,9383.53) 10173.65,9360.33 cw(c10196.85,9337.13) J5.A17@10196.85,9369.94 ; J5.A17@10196.85,9383.53 10158.32,9345 9820,9345 9724,9249 9724,8653 9661,8590
PXI_TRIG3: J5.A18 R84.2 | length 1934.4
  BottomLayer w8: 9148.4,8620.14 cw(c9118.26,8590) R84.2@9160.88,8590 ; 9153.15,8615.38 ccw(c9176.57,8638.8) R84.2@9176.57,8605.68 ; R84.2@9162.06,8606.48 cw(c9145.58,8590) R84.2@9168.88,8590 ; R84.2@9178.54,8590 9093,8675.54 9093,8921 9165,8993 9379,8993 9719,9333 9719,9382 9759,9422 10156.58,9422 J5.A18@10196.85,9462.27 ; J5.A18@10175.26,9462.27 cw(c10123.14,9462.27) 10159.99,9425.41 cw(c10196.85,9388.55) J5.A18@10196.85,9440.68 ; J5.A18@10183.26,9462.27 cw(c10150.45,9462.27) 10173.65,9439.07 cw(c10196.85,9415.87) J5.A18@10196.85,9448.68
